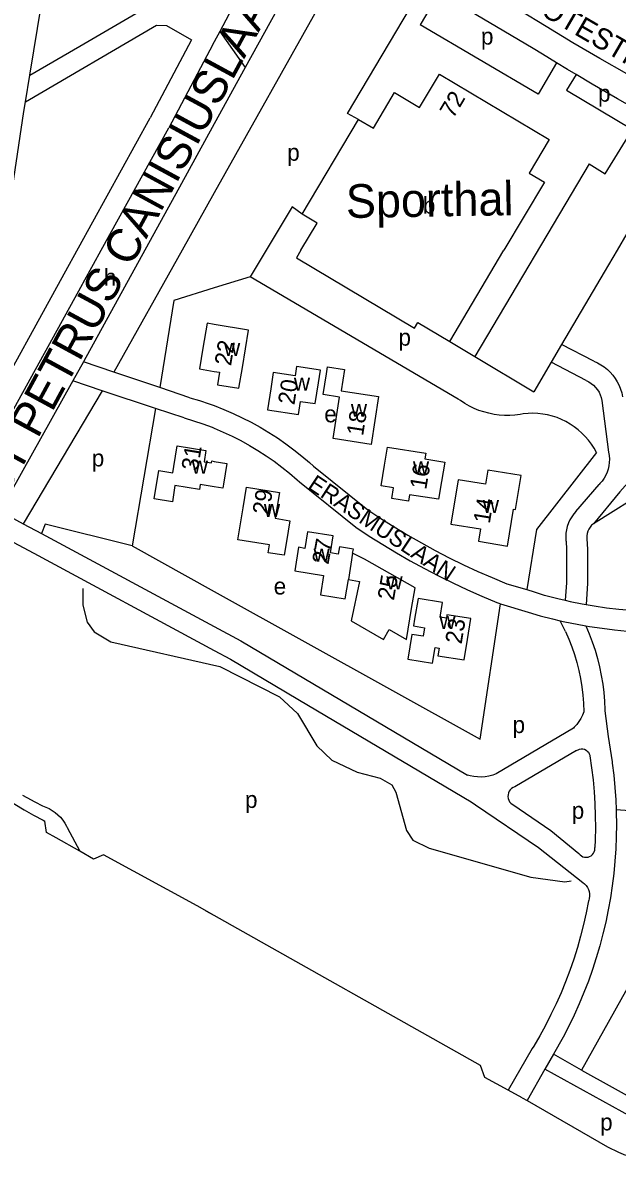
# Model space of a CAD drawing. Extents: x 162804 to 165059, y 381530 to 382901.
# Drawn here: x 163304.5 to 163445.8, y 381531.3 to 381804.1 of the extents above; entities that cross this region are included whole.
import ezdxf

# ---------------------------------------------------------------- set-up
doc = ezdxf.new("R2010")
doc.units = 0
for name, color, linetype in [('BLT_Basislijn', 7, 'Continuous'), ('BLT_Bebouwing', 7, 'Continuous'), ('BLT_Bebouwing_beschrifting', 7, 'Continuous'), ('BLT_Centroide', 7, 'Continuous'), ('BLT_Huisnummer', 7, 'Continuous'), ('BLT_Onderverdeling_panden', 7, 'Continuous'), ('BLT_Straatnaam', 7, 'Continuous'), ('BLT_Straatnaam_hoofdweg', 7, 'Continuous'), ('BLT_Straatnaam_verkleind', 7, 'Continuous'), ('BLT_Vlakafsluiter', 7, 'Continuous')]:
    doc.layers.add(name, color=color, linetype=linetype)

msp = doc.modelspace()

# ---------------------------------------------------------------- linework, layer by layer
at = {"layer": 'BLT_Basislijn'}
for p, q in [((163365.87, 381829.49), (163351.31, 381802.03)), ((163383.31, 381823.11), (163350, 381763.68)), ((163373.95, 381823.59), (163357.37, 381793.45)), ((163403.43, 381811.24), (163398.95, 381803.64)), ((163425.83, 381798.02), (163403.43, 381811.24)), ((163318.03, 381798.58), (163334.19, 381807.96)), ((163426.99, 381787.1), (163398.95, 381803.64)), ((163338.64, 381803.43), (163344.6, 381800.07)), ((163351.31, 381802.03), (163350, 381799.57)), ((163306.14, 381791.68), (163318.03, 381798.58)), ((163344.6, 381800.07), (163334.75, 381781.49)), ((163350, 381799.57), (163348.96, 381797.61)), ((163348.96, 381797.61), (163339.16, 381779.14)), ((163357.37, 381793.45), (163350, 381780.05)), ((163431.4, 381794.59), (163426.99, 381787.1)), ((163305.09, 381785.3), (163306.14, 381791.68)), ((163323.08, 381750), (163339.16, 381779.14)), ((163350, 381780.05), (163341.73, 381765.02)), ((163439.13, 381770.55), (163411.93, 381724.77)), ((163341.73, 381765.02), (163333.47, 381750)), ((163350, 381763.68), (163342.33, 381750)), ((163448.14, 381754), (163445.78, 381750)), ((163333.47, 381750), (163318.98, 381723.66)), ((163321.28, 381746.74), (163323.08, 381750)), ((163342.33, 381750), (163326.1, 381721.03)), ((163362.33, 381750), (163358.54, 381743.69)), ((163445.78, 381750), (163442.71, 381744.8)), ((163318.8, 381742.25), (163321.28, 381746.74)), ((163358.54, 381743.69), (163350, 381741.06)), ((163408.02, 381714.62), (163358.54, 381743.69)), ((163442.71, 381744.8), (163432.57, 381727.61)), ((163297.74, 381704.09), (163318.64, 381741.96)), ((163318.64, 381741.96), (163318.8, 381742.25)), ((163405.98, 381728.32), (163411.93, 381724.77)), ((163432.57, 381727.61), (163430.1, 381723.41)), ((163440.28, 381723.65), (163432.57, 381727.61)), ((163411.93, 381724.77), (163425.96, 381716.39)), ((163318.86, 381723.45), (163316.35, 381718.94)), ((163318.98, 381723.66), (163318.86, 381723.45)), ((163326.1, 381721.03), (163318.86, 381723.45)), ((163430.1, 381723.41), (163425.96, 381716.39)), ((163438.4, 381719.01), (163430.1, 381723.41)), ((163337.06, 381717.35), (163326.1, 381721.03)), ((163316.35, 381718.94), (163299.08, 381687.95)), ((163323.36, 381716.61), (163304.57, 381685)), ((163323.36, 381716.61), (163316.35, 381718.94)), ((163336.02, 381712.41), (163323.36, 381716.61)), ((163344.2, 381714.96), (163337.06, 381717.35)), ((163442.17, 381714.33), (163443.73, 381701.97)), ((163336.02, 381712.41), (163330.49, 381679.72)), ((163342.85, 381710.14), (163336.02, 381712.41)), ((163373.6, 381698.65), (163386.48, 381688.28)), ((163370.23, 381694.95), (163383.68, 381684.14)), ((163435.98, 381687.91), (163441.54, 381694.35)), ((163299.08, 381687.95), (163304.57, 381685)), ((163304.57, 381685), (163308.91, 381682.66)), ((163309.78, 381684.92), (163308.91, 381682.66)), ((163330.49, 381679.72), (163309.78, 381684.92)), ((163439.06, 381683.73), (163438.83, 381683.23)), ((163439.37, 381684.19), (163439.06, 381683.73)), ((163439.74, 381684.61), (163439.37, 381684.19)), ((163440.16, 381684.96), (163439.74, 381684.61)), ((163308.91, 381682.66), (163350, 381660.56)), ((163438.66, 381682.69), (163438.58, 381682.14)), ((163438.58, 381682.14), (163438.58, 381681.59)), ((163438.58, 381681.59), (163438.6, 381681.36)), ((163438.6, 381681.36), (163438.74, 381678.98)), ((163438.83, 381683.23), (163438.66, 381682.69)), ((163302.14, 381680.63), (163307.1, 381677.96)), ((163330.49, 381679.72), (163350, 381668.89)), ((163433.64, 381680.74), (163433.74, 381678.98)), ((163307.1, 381677.96), (163350, 381654.88)), ((163419.56, 381670.72), (163424.3, 381669.33)), ((163424.3, 381669.33), (163426.09, 381668.8)), ((163426.09, 381668.8), (163428.44, 381668.04)), ((163417.7, 381666.08), (163418.09, 381665.96)), ((163418.09, 381665.96), (163424.62, 381663.94)), ((163433.49, 381659.35), (163432.24, 381661.93)), ((163435.39, 381636.4), (163417.05, 381625.5)), ((163436.17, 381631.05), (163421.44, 381622.45)), ((163411.09, 381618.85), (163412.12, 381618.16)), ((163467.14, 381615.2), (163445.57, 381617)), ((163314.97, 381612.74), (163318.03, 381607.1)), ((163452.51, 381582.3), (163437.36, 381555.04)), ((163425.63, 381560.22), (163419.85, 381550.32)), ((163430.7, 381558.88), (163428.6, 381555.31)), ((163437.36, 381555.04), (163430.7, 381558.88)), ((163428.6, 381555.31), (163424.37, 381547.82)), ((163437.36, 381555.04), (163464.99, 381539.75)), ((163423.23, 381548.48), (163419.85, 381550.32)), ((163423.23, 381548.48), (163424.37, 381547.82)), ((163424.37, 381547.82), (163443.49, 381536.83))]:
    msp.add_line(p, q, dxfattribs=at)
for points in [[(163384.31, 381781.14), (163381.69, 381782.53), (163399.91, 381813.32)], [(163507.64, 381762.13), (163500.89, 381765.16), (163494.16, 381768.26), (163487.47, 381771.43), (163480.82, 381774.68), (163474.2, 381777.99), (163467.62, 381781.38), (163461.07, 381784.84), (163454.57, 381788.37), (163448.1, 381791.97), (163441.67, 381795.64), (163435.28, 381799.37), (163428.93, 381803.18), (163422.62, 381807.06), (163418.08, 381809.9)], [(163306.14, 381791.68), (163308.92, 381808.55)], [(163305.09, 381785.3), (163336.26, 381803.54), (163338.64, 381803.43)], [(163431.4, 381794.59), (163428.08, 381796.62), (163425.83, 381798.02)], [(163436.05, 381791.78), (163433.97, 381793.02), (163431.4, 381794.59)], [(163436.05, 381791.78), (163433.78, 381788.09), (163449.46, 381778.72)], [(163451.88, 381782.63), (163445.87, 381786.02), (163439.9, 381789.49), (163436.05, 381791.78)], [(163294.09, 381778.69), (163295.22, 381774.64), (163294.83, 381772.31), (163293.55, 381771.11), (163271.56, 381757.97), (163268.52, 381756.15), (163267.6, 381755.11), (163267.13, 381753.75), (163267.28, 381752.42), (163272.13, 381738.94), (163273.95, 381736.81), (163276.33, 381736.55), (163296.44, 381741.63), (163298.25, 381743.08), (163299.1, 381745.15), (163304.71, 381782.98), (163305.09, 381785.3)], [(163228.44, 381738.97), (163295.54, 381710.45), (163314.26, 381744.38), (163334.75, 381781.49)], [(163439.13, 381770.55), (163442.96, 381768.22), (163449.46, 381778.72)], [(163370.89, 381758.57), (163368.53, 381760.32), (163362.33, 381750)], [(163350, 381741.06), (163340.36, 381738.08), (163337.06, 381717.35)], [(163538.27, 381743.42), (163534.12, 381734.01), (163500, 381718.5), (163478.02, 381708.51), (163453.55, 381693.34), (163440.16, 381684.96)], [(163440.28, 381723.65), (163441.14, 381723.26), (163441.96, 381722.79), (163442.75, 381722.26), (163443.48, 381721.67), (163444.16, 381721.01), (163444.79, 381720.3), (163445.35, 381719.54), (163445.84, 381718.74), (163446.27, 381717.89), (163446.62, 381717.02), (163446.89, 381716.11), (163447.1, 381715.16)], [(163438.4, 381719.01), (163439.04, 381718.71), (163439.63, 381718.34), (163440.18, 381717.91), (163440.68, 381717.41), (163441.12, 381716.86), (163441.49, 381716.27), (163441.8, 381715.63), (163442.02, 381714.97), (163442.17, 381714.33)], [(163344.2, 381714.96), (163346.51, 381714.27), (163348.8, 381713.5), (163350, 381713.07)], [(163422.73, 381711), (163421.49, 381710.84), (163420.25, 381710.76), (163419.01, 381710.76), (163417.76, 381710.84), (163416.53, 381711), (163415.31, 381711.24), (163414.1, 381711.56), (163412.92, 381711.95), (163411.77, 381712.42), (163410.65, 381712.96), (163409.56, 381713.58), (163408.52, 381714.26), (163408.02, 381714.62)], [(163350, 381713.07), (163352.25, 381712.19), (163354.46, 381711.23), (163356.64, 381710.2), (163358.79, 381709.11), (163360.9, 381707.93), (163362.97, 381706.7), (163365, 381705.39), (163366.98, 381704.01), (163368.92, 381702.58), (163370.8, 381701.07), (163372.64, 381699.51), (163373.6, 381698.65)], [(163440.87, 381701.9), (163440.31, 381702.92), (163439.68, 381703.9), (163438.99, 381704.84), (163438.23, 381705.73), (163437.41, 381706.56), (163436.54, 381707.34), (163435.61, 381708.05), (163434.64, 381708.7), (163433.63, 381709.28), (163432.58, 381709.79), (163431.5, 381710.23), (163430.39, 381710.59), (163429.26, 381710.87), (163428.11, 381711.08), (163426.95, 381711.21), (163425.78, 381711.26), (163424.61, 381711.23), (163423.45, 381711.11), (163422.73, 381711)], [(163342.85, 381710.14), (163345.08, 381709.48), (163347.29, 381708.73), (163349.47, 381707.92), (163350, 381707.7)], [(163350, 381707.7), (163352.14, 381706.79), (163354.25, 381705.81), (163356.33, 381704.75), (163358.36, 381703.62), (163360.36, 381702.43), (163362.32, 381701.17), (163364.23, 381699.84), (163366.09, 381698.44), (163367.9, 381696.98), (163369.67, 381695.46), (163370.23, 381694.95)], [(163440.87, 381701.9), (163426.6, 381683.63), (163424.3, 381669.33)], [(163453.29, 381700.25), (163446.44, 381692.54), (163440.16, 381684.96)], [(163443.73, 381701.97), (163443.88, 381701.18), (163443.95, 381700.38), (163443.93, 381699.58), (163443.84, 381698.78), (163443.67, 381698), (163443.42, 381697.23), (163443.1, 381696.5), (163442.71, 381695.8), (163442.25, 381695.14), (163441.72, 381694.54), (163441.54, 381694.35)], [(163386.48, 381688.28), (163389.61, 381686.22), (163392.78, 381684.22), (163395.99, 381682.28), (163399.24, 381680.42), (163402.53, 381678.63), (163405.86, 381676.9), (163409.23, 381675.25), (163412.63, 381673.67), (163416.06, 381672.17), (163419.56, 381670.72)], [(163435.98, 381687.91), (163435.49, 381687.34), (163434.99, 381686.66), (163434.57, 381685.93), (163434.22, 381685.17), (163433.94, 381684.37), (163433.74, 381683.55), (163433.61, 381682.72), (163433.57, 381681.88), (163433.6, 381681.04), (163433.64, 381680.74)], [(163383.68, 381684.14), (163386.85, 381682.05), (163390.06, 381680.02), (163393.32, 381678.05), (163396.61, 381676.16), (163399.95, 381674.34), (163403.32, 381672.58), (163406.73, 381670.9), (163410.18, 381669.29), (163413.65, 381667.76), (163417.16, 381666.29), (163417.7, 381666.08)], [(163433.74, 381678.98), (163433.74, 381670.93), (163433.47, 381666.78)], [(163438.74, 381678.98), (163438.74, 381670.77), (163438.41, 381665.78)], [(163318.7, 381669.55), (163318.7, 381665.59), (163319.79, 381661.56), (163321.41, 381659.28), (163325.36, 381656.91), (163351.27, 381651.03), (163365.53, 381643.83), (163369.79, 381639.83), (163374.4, 381632.16), (163377.93, 381628.79), (163383.99, 381625.9), (163389.46, 381624.53), (163392.22, 381622.92), (163393.18, 381621.15), (163395.69, 381612.05), (163397.22, 381609.73), (163401.11, 381607.85), (163425.31, 381600.94), (163433.33, 381599.83), (163434.85, 381600.08)], [(163350, 381668.89), (163413.26, 381633.78), (163418.09, 381665.96)], [(163428.44, 381668.04), (163428.88, 381667.91), (163431.73, 381667.18), (163433.47, 381666.78)], [(163433.47, 381666.78), (163434.59, 381666.52), (163437.47, 381665.95), (163438.41, 381665.78)], [(163438.41, 381665.78), (163440.36, 381665.45), (163443.27, 381665.03), (163446.18, 381664.69), (163449.01, 381664.43)], [(163424.62, 381663.94), (163427.5, 381663.11), (163430.41, 381662.36), (163432.24, 381661.93)], [(163432.24, 381661.93), (163433.34, 381661.68), (163436.28, 381661.08), (163438.36, 381660.72)], [(163350, 381660.56), (163356.34, 381657.15), (163410.18, 381625.21)], [(163433.49, 381659.35), (163434.28, 381657.55), (163434.99, 381655.72), (163435.63, 381653.86), (163436.19, 381651.97), (163436.67, 381650.07), (163437.08, 381648.15), (163437.4, 381646.21), (163437.65, 381644.26), (163437.82, 381642.31), (163437.91, 381640.25)], [(163438.36, 381660.72), (163439.16, 381658.81), (163439.89, 381656.87), (163440.54, 381654.92), (163441.11, 381652.93), (163441.6, 381650.93), (163442.02, 381648.91), (163442.36, 381646.87), (163442.62, 381644.83), (163442.8, 381642.77), (163442.9, 381640.71), (163442.9, 381640.51)], [(163438.36, 381660.72), (163439.24, 381660.56), (163442.21, 381660.12), (163445.19, 381659.77), (163448.18, 381659.48), (163448.63, 381659.45)], [(163350, 381654.88), (163353.88, 381652.79), (163372.41, 381641.8)], [(163372.41, 381641.8), (163411.09, 381618.85)], [(163437.91, 381640.25), (163437.58, 381639.44), (163437.18, 381638.66), (163436.72, 381637.93), (163436.18, 381637.24), (163435.59, 381636.6), (163435.39, 381636.4)], [(163442.9, 381640.51), (163443.7, 381634.43), (163444.58, 381628.37), (163444.63, 381628.07)], [(163436.17, 381631.05), (163436.5, 381631.26), (163436.87, 381631.4), (163437.26, 381631.47), (163437.66, 381631.45), (163438.04, 381631.35), (163438.4, 381631.18), (163438.71, 381630.94), (163438.97, 381630.65), (163439.17, 381630.3), (163439.29, 381629.93), (163439.32, 381629.79)], [(163439.32, 381629.79), (163439.73, 381626.96), (163440.07, 381624.12), (163440.33, 381621.28), (163440.51, 381618.43), (163440.61, 381615.57), (163440.63, 381612.72), (163440.57, 381609.86), (163440.48, 381607.97)], [(163290.2, 381627.71), (163292.13, 381625.99), (163294.11, 381624.32), (163296.15, 381622.72), (163298.23, 381621.18), (163300.36, 381619.7), (163302.53, 381618.29), (163304.75, 381616.95), (163307.01, 381615.68), (163309.3, 381614.48), (163309.68, 381614.29)], [(163444.63, 381628.07), (163444.99, 381625.19), (163445.27, 381622.27), (163445.47, 381619.36), (163445.57, 381617)], [(163417.05, 381625.5), (163416.2, 381625.2), (163415.32, 381624.97), (163414.43, 381624.82), (163413.52, 381624.76), (163412.62, 381624.77), (163411.72, 381624.86), (163410.83, 381625.03), (163410.18, 381625.21)], [(163421.44, 381622.45), (163421.04, 381622.27), (163420.69, 381622.03), (163420.38, 381621.72), (163420.13, 381621.37), (163419.95, 381620.97), (163419.85, 381620.55), (163419.83, 381620.12), (163419.89, 381619.69), (163420.02, 381619.27), (163420.23, 381618.89), (163420.51, 381618.56), (163420.84, 381618.28), (163420.98, 381618.19)], [(163304.39, 381620.46), (163305.4, 381619.87), (163307.27, 381618.87), (163309.17, 381617.94), (163310.71, 381617.26)], [(163412.12, 381618.16), (163427.06, 381608.02), (163437.64, 381599.66)], [(163420.98, 381618.19), (163430.02, 381612.06), (163436.72, 381606.56)], [(163310.71, 381617.26), (163311.45, 381616.84), (163312.15, 381616.35), (163312.81, 381615.8), (163313.4, 381615.18), (163313.94, 381614.52), (163314.42, 381613.81), (163314.82, 381613.06), (163314.97, 381612.74)], [(163445.57, 381617), (163445.59, 381616.43), (163445.63, 381613.51), (163445.59, 381610.58), (163445.47, 381607.66), (163445.27, 381604.74), (163444.99, 381601.83), (163444.64, 381598.92), (163444.2, 381596.03), (163443.68, 381593.15), (163443.09, 381590.28), (163442.42, 381587.44), (163441.67, 381584.61), (163440.84, 381581.8), (163439.93, 381579.02), (163438.96, 381576.26), (163437.9, 381573.53), (163436.77, 381570.83), (163435.57, 381568.17), (163434.3, 381565.53), (163432.95, 381562.93), (163430.7, 381558.88)], [(163318.03, 381607.1), (163312.39, 381610.28), (163310.07, 381611.58), (163309.68, 381614.29)], [(163436.72, 381606.56), (163436.98, 381606.25), (163437.3, 381606), (163437.66, 381605.82), (163438.06, 381605.71), (163438.46, 381605.67), (163438.87, 381605.72), (163439.25, 381605.85), (163439.61, 381606.05), (163439.92, 381606.31), (163440.17, 381606.63), (163440.35, 381606.99), (163440.46, 381607.38), (163440.49, 381607.79), (163440.48, 381607.97)], [(163345.93, 381594.15), (163323.61, 381606.28), (163321.29, 381605.25), (163318.03, 381607.1)], [(163437.64, 381599.66), (163438.07, 381599.33), (163438.44, 381598.94), (163438.75, 381598.5), (163438.99, 381598.02), (163439.15, 381597.51), (163439.24, 381596.98), (163439.25, 381596.44), (163439.18, 381595.91), (163439.04, 381595.39), (163439, 381595.3)], [(163350, 381591.86), (163345.93, 381594.15)], [(163439, 381595.3), (163438.45, 381592.49), (163437.82, 381589.7), (163437.12, 381586.94), (163436.34, 381584.19), (163435.48, 381581.46), (163434.55, 381578.76), (163433.54, 381576.09), (163432.45, 381573.45), (163431.3, 381570.84), (163430.07, 381568.26), (163428.77, 381565.71), (163427.39, 381563.21), (163425.95, 381560.74), (163425.63, 381560.22)], [(163350, 381591.86), (163348.09, 381592.9)], [(163419.85, 381550.32), (163414.37, 381553.31), (163413.29, 381556.19), (163350, 381591.86)], [(163460.11, 381531.31), (163463.06, 381536.25), (163428.6, 381555.31)], [(163443.49, 381536.83), (163446.12, 381535.53), (163447.77, 381534.83)]]:
    msp.add_lwpolyline(points, dxfattribs=at)
at = {"layer": 'BLT_Bebouwing'}
for p, q in [((163370.89, 381758.57), (163384.31, 381781.14)), ((163370.6, 381750), (163369.53, 381748.2)), ((163405.98, 381728.32), (163418.87, 381750)), ((163369.53, 381748.2), (163397.58, 381731.51))]:
    msp.add_line(p, q, dxfattribs=at)
for points in [[(163384.31, 381781.14), (163387.82, 381779.06), (163392.85, 381787.5), (163398.8, 381783.96), (163403.52, 381791.89), (163429.67, 381776.34)], [(163429.67, 381776.34), (163424.91, 381768.33), (163428.5, 381766.19), (163418.87, 381750)], [(163370.6, 381750), (163374.44, 381756.46), (163370.89, 381758.57)], [(163397.58, 381731.51), (163398.37, 381732.84), (163405.98, 381728.32)], [(163350, 381732.37), (163348.26, 381732.66), (163347.28, 381726.73), (163346.47, 381721.8), (163350, 381721.22)], [(163350, 381721.22), (163351.23, 381721.01), (163350.74, 381718.05), (163355.84, 381717.21), (163356.66, 381722.15), (163358.12, 381731.03), (163350, 381732.37)], [(163374.76, 381718.48), (163375.22, 381721.48), (163369.56, 381722.36), (163369.22, 381720.17), (163364.03, 381720.97), (163363.42, 381717.03), (163362.65, 381712.09), (163369.98, 381710.95), (163370.46, 381714.09), (163373.99, 381713.54), (163374.76, 381718.48)], [(163387.31, 381703.83), (163378.23, 381705.23), (163379.75, 381715.08), (163375.87, 381715.68), (163376.64, 381720.62), (163376.9, 381722.32), (163380.95, 381721.69), (163380.16, 381716.6), (163389.08, 381715.22), (163387.31, 381703.83)], [(163350, 381693.79), (163346.64, 381694.34), (163346.45, 381693.16), (163340.64, 381694.08), (163340.03, 381690.23), (163335.71, 381690.91), (163336.77, 381697.65), (163340.16, 381697.11), (163340.36, 381698.56), (163341.17, 381703.49), (163348, 381702.38), (163347.57, 381699.72), (163349.33, 381699.44), (163349.4, 381699.91), (163350, 381699.82)], [(163404.05, 381695.06), (163403.35, 381690.8), (163396.41, 381691.89), (163396.15, 381690.38), (163392.2, 381691.02), (163392.6, 381693.5), (163389.64, 381693.98), (163390.45, 381698.92), (163391.15, 381703.21), (163400.27, 381701.79), (163400.04, 381700.44), (163404.81, 381699.65), (163404.05, 381695.06)], [(163350, 381699.82), (163353.01, 381699.33), (163352.21, 381694.39), (163352.06, 381693.46), (163350, 381693.79)], [(163406.24, 381684.9), (163413.32, 381683.78), (163412.83, 381680.81), (163419.71, 381679.68), (163421.16, 381688.49), (163421.66, 381688.41), (163422.98, 381696.42), (163415.05, 381697.73), (163414.49, 381694.38), (163407.98, 381695.45), (163406.24, 381684.9)], [(163367.17, 381680.78), (163366.63, 381677.48), (163362.84, 381678.09), (163363.14, 381679.95), (163355.59, 381681.17), (163356.83, 381688.75), (163357.63, 381693.69), (163365.48, 381692.41), (163364.48, 381686.28), (163367.97, 381685.71), (163367.17, 381680.78)], [(163372.19, 381683.07), (163371.55, 381679.13), (163370.03, 381679.38), (163369.12, 381673.78), (163375.96, 381672.66), (163375.22, 381668.12), (163381.13, 381667.16), (163381.88, 381671.7)], [(163382.9, 381677.96), (163383.06, 381678.96), (163379.78, 381679.49), (163379.49, 381677.75), (163377.59, 381678.06), (163378.24, 381682.08), (163372.19, 381683.07)], [(163396.93, 381664.82), (163397.76, 381669.74), (163385.72, 381676.59), (163382.9, 381677.96)], [(163381.88, 381671.7), (163384.56, 381671.27), (163382.51, 381661.88), (163390.25, 381657.48), (163391.59, 381659.82), (163395.7, 381657.49), (163396.93, 381664.82)], [(163410.23, 381657.49), (163411.03, 381662.42), (163405.32, 381663.35), (163405.2, 381662.57), (163403.72, 381662.81), (163404.29, 381666.28), (163398.44, 381667.23), (163397.64, 381662.29), (163397.38, 381660.68), (163400, 381660.25), (163399.67, 381658.22), (163396.96, 381658.66), (163396, 381652.77), (163401.88, 381651.81), (163402.49, 381655.54), (163403.48, 381655.38), (163403.19, 381653.6), (163409.43, 381652.59), (163410.23, 381657.49)]]:
    msp.add_lwpolyline(points, dxfattribs=at)
at = {"layer": 'BLT_Onderverdeling_panden'}
msp.add_line((163382.9, 381677.96), (163381.88, 381671.7), dxfattribs=at)
at = {"layer": 'BLT_Vlakafsluiter'}
msp.add_line((163351.31, 381802.03), (163357.37, 381793.45), dxfattribs=at)

# ---------------------------------------------------------------- texts
at = {"layer": 'BLT_Bebouwing_beschrifting'}
msp.add_text('Sporthal', height=8, rotation=1, dxfattribs=at).set_placement((163381.36, 381757.67))
at = {"layer": 'BLT_Centroide'}
for s, p in [('p', (163413.42, 381798.91)), ('p', (163441.25, 381785.34)), ('p', (163367.33, 381771.29)), ('b', (163399.59, 381758.72)), ('h', (163323.7, 381741.59)), ('p', (163393.79, 381727.33)), ('w', (163352.3, 381724.91)), ('w', (163368.91, 381716.66)), ('e', (163376.15, 381709.1)), ('w', (163382.47, 381710.41)), ('p', (163320.85, 381698.61)), ('w', (163344.63, 381696.88)), ('w', (163397.23, 381696.78)), ('w', (163361.78, 381686.58)), ('w', (163413.84, 381687.56)), ('w', (163373.6, 381675.98)), ('e', (163364.12, 381668.15)), ('w', (163390.92, 381669.38)), ('w', (163403.52, 381659.98)), ('p', (163420.93, 381635.21)), ('p', (163357.3, 381617.41)), ('p', (163435, 381614.82)), ('p', (163441.75, 381540.73))]:
    msp.add_text(s, height=4, dxfattribs=at).set_placement(p)
at = {"layer": 'BLT_Huisnummer'}
for s, rotation, p in [('72', 59.2558, (163406.8, 381781.17)), ('22', 80.6496, (163353.96, 381722.39)), ('20', 81.2025, (163369.04, 381713.11)), ('18', 81.2126, (163385.37, 381705.73)), ('31', 80.7676, (163346.06, 381697.42)), ('16', 80.645, (163400.39, 381692.97)), ('29', 80.7604, (163362.97, 381686.94)), ('14', 80.5593, (163415.5, 381684.87)), ('27', 79.5521, (163377.12, 381675.15)), ('25', 80.4236, (163392.7, 381666.61)), ('23', 80.7676, (163408.81, 381656.24))]:
    msp.add_text(s, height=4, rotation=rotation, dxfattribs=at).set_placement(p)
at = {"layer": 'BLT_Straatnaam'}
msp.add_text('GEERT GROOTESTRAAT', height=5, rotation=329.8331, dxfattribs=at).set_placement((163392.63, 381826.32))
at = {"layer": 'BLT_Straatnaam_hoofdweg'}
msp.add_text('ST PETRUS CANISIUSLAAN', height=8, rotation=61.4841, dxfattribs=at).set_placement((163300.05, 381690.41))
at = {"layer": 'BLT_Straatnaam_verkleind'}
msp.add_text('ERASMUSLAAN', height=4, rotation=326.396, dxfattribs=at).set_placement((163371.96, 381693.51))

doc.saveas('drawing.dxf')
